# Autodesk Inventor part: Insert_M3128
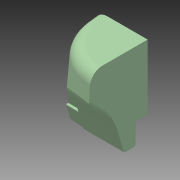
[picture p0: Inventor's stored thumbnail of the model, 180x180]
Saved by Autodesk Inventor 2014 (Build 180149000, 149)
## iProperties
Created: 2009-02
Part Number: Insert_M3128
Document SubType Name: Modeling
Designer: gaom
Density: 1 g/cm^3
Material: Generic
Appearance: Green Pastel
Author: gaom
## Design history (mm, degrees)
derived "Mold Top_Top_IS.ipt"
  sketch "Sketch2"
    geometry: L1 (-0.663, -0.146)-(-2.471, -0.66); L2 (-2.617, -0.854)-(-2.617, -1.914); L3 (-2.415, -2.139)-(-0.609, -2.139); L4 (0, -2.018)-(0, 0); L5 (-0.663, -0.146)-(0.001, 0.043); L6 (-0.609, -2.139)-(0, -2.139); L7 (0, -2.139)-(0, -3.639); L8 (0, -3.639)-(8.5, -3.639); L9 (8.5, -3.639)-(8.5, 1.947); L10 (4.806, 3.447)-(4.806, 3.947); L11 (4.806, 3.947)-(6.5, 3.947); A1 r 8.855 centre (-2.424, 8.56) between (0.001, 0.043) and (4.806, 3.447); A2 r 2 centre (6.5, 1.947) between (8.5, 1.947) and (6.5, 3.947); 10 further points; 2 other entities
    constraints: 22 end point, 4 point on circle, 2 centre point, 17 other
workplane "Work Plane1"
sketch "Sketch3"
  geometry: L1 (0.146, -0.663)-(0.66, -2.471) reference; L2 (0.854, -2.617)-(1.914, -2.617) reference; L3 (2.139, -2.415)-(2.139, -0.609) reference; L4 (0.146, -0.663)-(-0.043, 0.001) reference; L5 (2.139, -0.609)-(2.139, 0) reference; L6 (2.139, 0)-(3.639, 0) reference; L7 (3.639, 0)-(3.639, 8.5) reference; L8 (3.639, 8.5)-(-1.947, 8.5) reference; L9 (-3.447, 4.806)-(-3.947, 4.806) reference; L10 (-3.947, 4.806)-(-3.947, 6.5) reference; A1 r 8.855 centre (-8.56, -2.424) between (-0.043, 0.001) and (-3.447, 4.806) reference; A2 r 2 centre (-1.947, 6.5) between (-1.947, 8.5) and (-3.947, 6.5) reference; 3 further points; 2 other entities
  constraints: 2 other
feature "Surface1"
extrude "Extrusion1" join sketch "Sketch3" stored distance "d2" = 0.13; taper "d3" = 0 deg
body "Solid2"
body "Srf1"
other parameters: "d1" = 0
